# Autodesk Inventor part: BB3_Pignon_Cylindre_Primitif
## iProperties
Created: 2009-02
Part Number: BB3_Pignon_Cylindre_Primitif
Document SubType Name: Modeling
Designer: Alex_Cyril
Author: Alex_Cyril
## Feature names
1. Extrusion1
